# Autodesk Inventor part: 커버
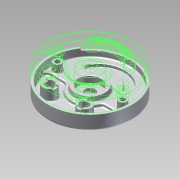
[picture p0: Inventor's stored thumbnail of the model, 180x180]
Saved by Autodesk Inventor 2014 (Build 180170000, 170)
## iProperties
Company: 한국ATC센터
Created: 2015-04
Part Number: 커버
Document SubType Name: Modeling
Designer: KYOUNG IL JANG
Density: 2.71 g/cm^3
Material: 알루미늄-6061
Mass: 1067.78 g
Surface Area: 1019.64 cm^2
Volume: 394.015 cm^3
Appearance: 매끄러움 - 흰색
Author: KYOUNG IL JANG
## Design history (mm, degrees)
sketch "스케치1"
  geometry: L1 (-59, -19)-(-59, 19); L2 (59, 19)-(59, -19); L3 (-41, 19)-(-41, -19); L4 (41, -19)-(41, 19); L5 (38.527, 33.023)-(55.442, 39.179); L6 (-38.527, 33.023)-(-55.442, 39.179); C1 r 90 at (0, 0); C2 r 95 at (0, 0); A1 r 59 centre (0, 19) between (59, 19) and (-59, 19); A2 r 59 centre (0, -19) between (-59, -19) and (59, -19); A3 r 41 centre (0, -19) between (-41, -19) and (41, -19); A4 r 41 centre (0, 19) between (41, 19) and (-41, 19); 2 further points
  constraints: 12 end point, 12 point on circle, 6 centre point, 4 tangent, 2 parallel, 2 point on line, 1 coincident, 1 horizontal alignment, 1 midpoint, 1 vertical, 1 vertical alignment, 3 other
  dimensions: "d2" = 180 diameter of C1; "d3" = 156 dimension on A2 A1; "d4" = 118 distance between parallel lines of L2 L1; "d5" = 18 distance between parallel lines of L2 L4; "d8" = 190 diameter of C2; "d120" = 140 deg angle of L6 L5; "d121" = 110 deg dimension on A1.centre point (0, 0) L5.end
extrude "돌출1" new body sketch "스케치1" distance "d6" = 14; taper "d7" = 0 deg
extrude "돌출2" join sketch "스케치1" distance "d9" = 13; taper "d10" = 0 deg
extrude "돌출3" cut sketch "스케치1" distance "d11" = 7; taper "d12" = 0 deg
sketch "스케치2"
  geometry: C1 r 11.5 at (0, 0); 1 further point
  constraints: 1 centre point, 1 coincident
  dimensions: "d13" = 23 diameter of C1
extrude "돌출4" cut sketch "스케치2" stored distance "d14" = 7; taper "d15" = 0 deg
fillet "모깎기1"
fillet "모깎기2"
sketch "스케치3"
  geometry: L1 (-73.724, 51.622)-(-77.819, 54.49); L2 (73.724, 51.622)-(77.819, 54.49); L3 (0, 0)-(0, -90); A1 r 95 centre (0, 0) between (-77.819, 54.49) and (77.819, 54.49) reference; A2 r 90 centre (0, 0) between (-73.724, 51.622) and (73.724, 51.622) reference; 1 further point
  constraints: 6 end point, 5 point on circle, 1 point on line, 1 vertical, 1 other
  dimensions: "d16" = 250 deg dimension on L2 L1
extrude "돌출5" join sketch "스케치3" distance "d17" = 5; taper "d18" = 0 deg
hole "구멍1" diameter "d21" = 50; stored, may be unused: countersink angle "d25" = 90 deg, drill point angle "d27" = 0 deg; dims "d19" = 10, "d20" = 10, "d22" = 6, "d23" = 4, "d24" = 2, "d26" = 5
fillet "모깎기3" dims "d28" = 0.3
fillet "모깎기5" dims "d30" = 3
sketch "스케치4"
  geometry: C1 r 35 at (0, 0); C2 r 25 at (0, 0); 1 further point
  constraints: 2 centre point, 1 coincident
  dimensions: "d32" = 70 diameter of C1 (derived); "d36" = 10 radial gap between concentric circles of C1 C2
extrude "돌출6" join sketch "스케치4" distance "d33" = 10; taper "d34" = 0 deg
feature "면 기울기2" dims angle "d37" = 10 deg
chamfer "모따기1" distance "d39" = 1; stored, may be unused: second distance "d40" = 2, angle "d41" = 45 deg
fillet "모깎기7" dims "d42" = 5
sketch "스케치5"
  geometry: L1 (-40.249, -12)-(-89.196, -12); L2 (40.249, -12)-(89.196, -12); A1 r 90 centre (0, 0) between (-89.196, -12) and (89.196, -12) reference; A2 r 42 centre (0, 0) between (-40.249, -12) and (40.249, -12); 1 further point
  constraints: 4 end point, 4 point on circle, 1 centre point, 1 collinear, 1 horizontal, 1 point on line
  dimensions: "d43" = 48 radial gap between concentric circles of A1 A2; "d44" = 12 distance from line of point (0, 0) L1
extrude "돌출7" cut sketch "스케치5" stored distance "d45" = 10; taper "d46" = 0 deg
fillet "모깎기8" dims "d47" = 10
chamfer "모따기2" distance "d49" = 1; stored, may be unused: second distance "d50" = 2, angle "d51" = 45 deg
sketch "스케치7"
  geometry: L1 (36.062, 36.062)-(50.912, 50.912); L2 (-36.062, 36.062)-(-50.912, 50.912); A1 r 72 centre (0, 0) between (50.912, 50.912) and (-50.912, 50.912); A2 r 51 centre (0, 0) between (36.062, 36.062) and (-36.062, 36.062); 1 further point
  constraints: 8 point on circle, 4 end point, 2 centre point, 2 point on line, 1 coincident, 1 horizontal alignment
  dimensions: "d54" = 72 radius of A1; "d55" = 21 radial gap between concentric circles of A1 A2; "d56" = 90 deg angle of L2 L1
extrude "돌출8" join sketch "스케치7" distance "d57" = 5; taper "d58" = 0 deg
fillet "모깎기10" dims "d59" = 5
fillet "모깎기11" dims "d60" = 5
fillet "모깎기12" dims "d61" = 3
sketch "스케치6"
  geometry: C1 r 68 at (0, 0); 1 further point
  constraints: 1 centre point, 1 other
  dimensions: "d119" = 136 diameter of C1
feature "엠보싱1" sketch "스케치6" dims "d62" = 0.5, "d63" = 0
sketch "스케치8"
  geometry: C1 r 9 at (74, 0); C2 r 9 at (-74, 0); A1 r 74 centre (0, 0) between (74, 0) and (-74, 0); 1 further point
  constraints: 3 centre point, 2 horizontal alignment, 2 point on circle, 1 coincident, 1 equal radius
  dimensions: "d64" = 18 diameter of C1; "d65" = 148 diameter of A1
extrude "돌출9" join sketch "스케치8" stored distance "d66" = 5; taper "d67" = 0 deg
sketch "스케치11"
  geometry: C1 r 15 at (40, -52); C2 r 15 at (-40, -52); 1 further point
  constraints: 2 centre point, 1 equal radius, 1 horizontal alignment
  dimensions: "d83" = 52 vertical distance of point (0, 0) C1.centre; "d84" = 80 distance of C2.centre C1.centre; "d85" = 40 horizontal distance of point (0, 0) C1.centre (= 0.5 x d84); "d86" = 30 diameter of C1
extrude "돌출10" join sketch "스케치11" stored distance "d87" = 5; taper "d88" = 0 deg
node "구멍3"
node "구멍5"
hole "구멍6" diameter "d93" = 20; stored, may be unused: countersink angle "d97" = 90 deg, drill point angle "d99" = 118 deg; dims "d91" = 10, "d92" = 10, "d94" = 6, "d95" = 4, "d96" = 2, "d98" = 8
hole "구멍7" diameter "d102" = 20; stored, may be unused: countersink angle "d106" = 90 deg, drill point angle "d108" = 118 deg; dims "d100" = 10, "d101" = 10, "d103" = 6, "d104" = 4, "d105" = 2, "d107" = 8
sketch "스케치13"
  geometry: L1 (6, -13.748)-(6, -8); L2 (6, 8)-(6, 13.748); L3 (-6, -13.748)-(-6, -8); L4 (-6, 8)-(-6, 13.748); L5 (-66.252, -6)-(-72, -6); L6 (-88, -6)-(-93.748, -6); L7 (-66.252, 6)-(-72, 6); L8 (-88, 6)-(-93.748, 6); A1 r 15 centre (0, 0) between (6, -13.748) and (6, 13.748) reference; A2 r 10 centre (0, 0) between (6, -8) and (6, 8) reference; A3 r 15 centre (-80, 0) between (-66.252, -6) and (-93.748, -6) reference; A4 r 10 centre (-80, 0) between (-72, -6) and (-88, -6) reference; 1 further point
  constraints: 16 end point, 16 point on circle, 4 equal length, 3 collinear, 2 point on line, 1 perpendicular, 1 vertical
  dimensions: "d109" = 12 distance between parallel lines of L3 L1; "d110" = 6 distance from line of A1.centre L1 (= 0.5 x d109); "d111" = 12 distance between parallel lines of L7 L5; "d112" = 6 distance from line of A3.centre L5 (= 0.5 x d111)
extrude "돌출12" cut sketch "스케치13" distance "d113" = 3; taper "d114" = 0 deg
fillet "모깎기13" dims "d115" = 3
fillet "모깎기14" dims "d116" = 1
node "솔리드1"
sketch "스케치9"
  geometry: 1 further point
hole "구멍2" sketch "스케치9" diameter "d68" = 11; stored, may be unused: countersink angle "d72" = 90 deg, drill point angle "d74" = 0 deg; dims "d69" = 6, "d70" = 18, "d71" = 11, "d73" = 8
sketch "스케치10"
  geometry: 1 further point
hole "구멍4" sketch "스케치10" diameter "d75" = 11; stored, may be unused: countersink angle "d79" = 90 deg, drill point angle "d81" = 0 deg; dims "d76" = 6, "d77" = 18, "d78" = 11, "d80" = 8
